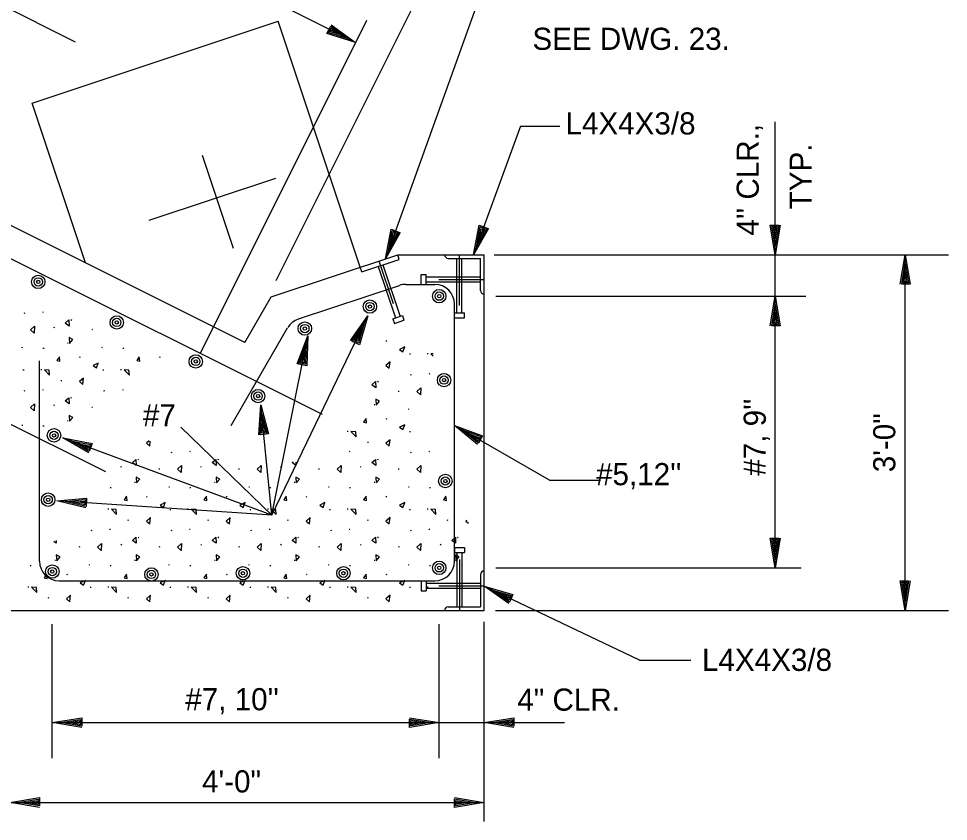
# Model space of a CAD drawing. Extents: x 6 to 106, y 3 to 74.
# Drawn here: x 89.14 to 104.82, y 24.53 to 38.07 of the extents above; entities that cross this region are included whole.
import ezdxf

# ---------------------------------------------------------------- set-up
doc = ezdxf.new("R2010")
doc.units = 0
for name, color, linetype in [('Level 22', 7, 'Continuous'), ('Level 25', 7, 'Continuous'), ('Level 3', 7, 'Continuous'), ('Level 44', 7, 'Continuous'), ('Level 50', 7, 'Continuous')]:
    doc.layers.add(name, color=color, linetype=linetype)

msp = doc.modelspace()

# ---------------------------------------------------------------- linework, layer by layer
at = {"layer": 'Level 22'}
for p, q in [((94.822, 37.665), (82.747, 43.702)), ((90.1, 37.67), (82.326, 41.557)), ((92.955, 32.603), (79.753, 39.204)), ((96.004, 38.701), (93.476, 33.644)), ((94.265, 31.389), (80.275, 38.384)), ((96.855, 38.273), (95.329, 34.019)), ((95.008, 38.037), (92.2, 32.422)), ((97.603, 36.251), (96.813, 34.086)), ((97.603, 36.251), (98.266, 36.251)), ((101.9, 34.086), (101.9, 36.324)), ((90.607, 30.423), (79.157, 36.148)), ((97.159, 34.086), (104.821, 34.086)), ((95.203, 33.889), (95.493, 33.019)), ((95.216, 33.981), (95.456, 33.262)), ((95.282, 33.915), (95.572, 33.046)), ((97.187, 33.387), (102.416, 33.387)), ((95.453, 33.006), (95.48, 32.927)), ((95.611, 33.059), (95.638, 32.98)), ((93.409, 29.696), (91.876, 31.177)), ((98.09, 30.286), (98.955, 30.286)), ((97.187, 28.806), (102.339, 28.806)), ((99.611, 27.249), (96.991, 28.495)), ((97.18, 28.086), (104.821, 28.086)), ((89.707, 25.596), (89.707, 27.857)), ((99.611, 27.249), (100.476, 27.249)), ((89.707, 26.195), (96.233, 26.195)), ((96.233, 26.195), (96.991, 26.195)), ((96.991, 26.195), (98.347, 26.195)), ((88.991, 24.85), (96.991, 24.85))]:
    msp.add_line(p, q, dxfattribs=at)
for centre, radius, start, end in [((96.386, 34.086), 0.0625, 180, 270), ((95.667, 33.253), 0.333, 90, 108.4348), ((96.157, 33.253), 0.333, 0, 90), ((96.991, 33.482), 0.0625, 180, 270), ((93.965, 32.685), 0.333, 108.435, 149.9988), ((89.824, 28.92), 0.333, 180, 270), ((96.157, 28.92), 0.333, 270, 0), ((96.991, 28.691), 0.0625, 90, 180), ((96.386, 28.086), 0.0625, 90, 180)]:
    msp.add_arc(centre, radius, start, end, dxfattribs=at)
at = {"layer": 'Level 25'}
for p, q in [((89.366, 36.643), (93.516, 38.026)), ((94.9, 33.876), (93.516, 38.026)), ((90.264, 33.949), (89.366, 36.643)), ((92.761, 34.193), (92.238, 35.761)), ((91.341, 34.666), (93.476, 35.378)), ((93.401, 33.376), (95.532, 34.086)), ((95.532, 34.086), (96.991, 34.086)), ((95.559, 34.007), (95.532, 34.086)), ((96.574, 33.227), (96.574, 34.086)), ((96.991, 28.086), (96.991, 34.086)), ((101.9, 33.387), (101.9, 34.086)), ((104.092, 28.086), (104.092, 34.086)), ((94.926, 33.797), (94.9, 33.876)), ((94.926, 33.797), (95.559, 34.007)), ((96.386, 34.024), (96.928, 34.024)), ((96.532, 33.107), (96.532, 34.024)), ((96.616, 33.107), (96.616, 34.024)), ((96.928, 33.482), (96.928, 34.024)), ((95.928, 33.586), (95.928, 33.753)), ((95.928, 33.753), (96.011, 33.753)), ((96.011, 33.586), (96.011, 33.753)), ((93.859, 33.002), (95.562, 33.569)), ((95.667, 33.586), (96.157, 33.586)), ((95.928, 33.586), (96.011, 33.586)), ((96.011, 33.711), (96.928, 33.711)), ((96.011, 33.628), (96.928, 33.628)), ((96.227, 33.67), (96.991, 33.67)), ((92.955, 32.603), (93.401, 33.376)), ((96.491, 28.92), (96.491, 33.253)), ((101.9, 28.806), (101.9, 33.387)), ((96.491, 33.107), (96.657, 33.107)), ((96.491, 33.024), (96.491, 33.107)), ((96.657, 33.024), (96.657, 33.107)), ((95.453, 33.006), (95.611, 33.059)), ((95.48, 32.927), (95.638, 32.98)), ((96.491, 33.024), (96.657, 33.024)), ((92.725, 31.205), (93.676, 32.852)), ((89.491, 28.92), (89.491, 32.294)), ((96.491, 29.149), (96.657, 29.149)), ((96.491, 29.149), (96.491, 29.066)), ((96.491, 29.066), (96.657, 29.066)), ((96.532, 29.066), (96.532, 28.149)), ((96.616, 29.066), (96.616, 28.149)), ((96.657, 29.149), (96.657, 29.066)), ((96.574, 28.946), (96.574, 28.086)), ((89.824, 28.586), (96.157, 28.586)), ((95.928, 28.586), (95.928, 28.42)), ((95.928, 28.586), (96.011, 28.586)), ((96.011, 28.586), (96.011, 28.42)), ((96.011, 28.545), (96.928, 28.545)), ((96.928, 28.691), (96.928, 28.149)), ((95.928, 28.42), (96.011, 28.42)), ((96.011, 28.461), (96.928, 28.461)), ((96.227, 28.503), (96.991, 28.503)), ((88.991, 28.086), (96.991, 28.086)), ((96.386, 28.149), (96.928, 28.149)), ((96.233, 25.596), (96.233, 27.857)), ((96.991, 24.53), (96.991, 27.893))]:
    msp.add_line(p, q, dxfattribs=at)
at = {"layer": 'Level 3'}
for p, q in [((93.409, 29.696), (95.028, 33.054)), ((95.028, 33.054), (95.028, 33.054)), ((94.968, 32.929), (94.968, 32.929)), ((93.409, 29.696), (94.016, 32.717)), ((94.016, 32.717), (94.016, 32.717)), ((93.989, 32.581), (93.989, 32.581)), ((93.409, 29.696), (93.224, 31.552)), ((93.224, 31.552), (93.224, 31.552)), ((93.237, 31.414), (93.237, 31.414)), ((93.409, 29.696), (89.884, 30.996)), ((89.884, 30.996), (89.884, 30.996)), ((90.014, 30.948), (90.014, 30.948)), ((93.409, 29.696), (89.783, 29.933)), ((89.783, 29.933), (89.783, 29.933)), ((89.921, 29.924), (89.921, 29.924))]:
    msp.add_line(p, q, dxfattribs=at)
for points in [[(94.737, 32.641), (95.028, 33.054), (94.886, 32.569), (94.759, 32.63), (94.968, 32.929), (94.871, 32.6), (94.79, 32.639), (94.91, 32.809), (94.857, 32.631), (94.823, 32.647), (94.85, 32.684)], [(93.837, 32.244), (94.016, 32.717), (93.999, 32.211), (93.86, 32.239), (93.989, 32.581), (93.977, 32.238), (93.888, 32.256), (93.963, 32.45), (93.955, 32.264), (93.919, 32.271), (93.935, 32.314)], [(93.191, 31.048), (93.224, 31.552), (93.355, 31.064), (93.215, 31.05), (93.237, 31.414), (93.327, 31.083), (93.237, 31.074), (93.251, 31.282), (93.298, 31.102), (93.261, 31.098), (93.264, 31.144)], [(90.323, 30.746), (89.884, 30.996), (90.38, 30.901), (90.331, 30.768), (90.014, 30.948), (90.351, 30.883), (90.32, 30.798), (90.139, 30.901), (90.322, 30.865), (90.309, 30.83), (90.269, 30.854)], [(90.275, 29.818), (89.783, 29.933), (90.286, 29.983), (90.276, 29.842), (89.921, 29.924), (90.263, 29.957), (90.257, 29.867), (90.054, 29.915), (90.24, 29.932), (90.237, 29.895), (90.192, 29.906)]]:
    msp.add_lwpolyline(points, dxfattribs=at)
at = {"layer": 'Level 44'}
for p, q in [((89.244, 33.101), (89.226, 33.096)), ((89.555, 33.119), (89.542, 33.114)), ((90.037, 32.978), (90.022, 32.987)), ((89.747, 32.854), (89.733, 32.86)), ((90.387, 32.822), (90.372, 32.82)), ((95.349, 32.631), (95.333, 32.623)), ((89.208, 32.517), (89.195, 32.519)), ((89.567, 32.505), (89.549, 32.505)), ((89.977, 32.595), (89.964, 32.596)), ((90.555, 32.517), (90.542, 32.519)), ((90.914, 32.505), (90.896, 32.505)), ((90.178, 32.36), (90.162, 32.352)), ((91.524, 32.36), (91.508, 32.352)), ((95.747, 32.41), (95.729, 32.41)), ((96.046, 32.416), (96.029, 32.416)), ((89.23, 32.138), (89.212, 32.138)), ((89.528, 32.145), (89.511, 32.145)), ((90.576, 32.138), (90.558, 32.138)), ((90.875, 32.145), (90.858, 32.145)), ((95.762, 32.061), (95.744, 32.056)), ((96.072, 32.079), (96.059, 32.074)), ((89.868, 31.958), (89.85, 31.961)), ((95.208, 31.937), (95.193, 31.946)), ((89.244, 31.789), (89.226, 31.784)), ((89.555, 31.807), (89.542, 31.802)), ((90.591, 31.789), (90.573, 31.784)), ((90.901, 31.807), (90.888, 31.802)), ((95.558, 31.781), (95.543, 31.78)), ((89.747, 31.542), (89.733, 31.549)), ((90.037, 31.666), (90.022, 31.675)), ((95.148, 31.554), (95.135, 31.555)), ((90.387, 31.51), (90.372, 31.509)), ((95.726, 31.476), (95.713, 31.479)), ((89.977, 31.283), (89.964, 31.284)), ((95.349, 31.319), (95.333, 31.311)), ((89.208, 31.205), (89.195, 31.207)), ((89.567, 31.194), (89.549, 31.194)), ((94.699, 31.104), (94.682, 31.104)), ((95.747, 31.098), (95.729, 31.098)), ((98.09, 30.286), (96.491, 31.208)), ((95.039, 30.918), (95.021, 30.921)), ((91.722, 30.749), (91.704, 30.744)), ((92.032, 30.767), (92.019, 30.762)), ((94.726, 30.767), (94.713, 30.762)), ((95.762, 30.749), (95.744, 30.744)), ((96.07, 30.766), (96.059, 30.762)), ((91.168, 30.626), (91.153, 30.635)), ((92.515, 30.626), (92.5, 30.635)), ((95.208, 30.626), (95.193, 30.635)), ((90.878, 30.502), (90.864, 30.508)), ((91.518, 30.47), (91.503, 30.468)), ((92.225, 30.502), (92.21, 30.508)), ((92.864, 30.47), (92.85, 30.468)), ((93.571, 30.502), (93.557, 30.508)), ((94.211, 30.47), (94.196, 30.468)), ((94.918, 30.502), (94.904, 30.508)), ((95.558, 30.47), (95.543, 30.468)), ((90.698, 30.153), (90.68, 30.153)), ((91.108, 30.243), (91.095, 30.244)), ((91.686, 30.165), (91.673, 30.167)), ((92.045, 30.153), (92.027, 30.153)), ((92.455, 30.243), (92.442, 30.244)), ((93.033, 30.165), (93.019, 30.167)), ((93.391, 30.153), (93.373, 30.153)), ((93.802, 30.243), (93.788, 30.244)), ((94.379, 30.165), (94.366, 30.167)), ((94.738, 30.153), (94.72, 30.153)), ((95.148, 30.243), (95.135, 30.244)), ((95.726, 30.165), (95.713, 30.167)), ((96.085, 30.153), (96.067, 30.153)), ((91.309, 30.008), (91.293, 30)), ((92.655, 30.008), (92.639, 30)), ((94.002, 30.008), (93.986, 30)), ((95.349, 30.008), (95.333, 30)), ((90.659, 29.793), (90.642, 29.793)), ((91.707, 29.786), (91.689, 29.786)), ((92.006, 29.793), (91.989, 29.793)), ((93.054, 29.786), (93.036, 29.786)), ((93.353, 29.793), (93.336, 29.793)), ((94.401, 29.786), (94.383, 29.786)), ((94.699, 29.793), (94.682, 29.793)), ((95.747, 29.786), (95.729, 29.786)), ((96.046, 29.793), (96.029, 29.793)), ((90.999, 29.606), (90.981, 29.609)), ((92.345, 29.606), (92.328, 29.609)), ((93.692, 29.606), (93.675, 29.609)), ((95.039, 29.606), (95.021, 29.609)), ((96.385, 29.606), (96.368, 29.609)), ((90.375, 29.437), (90.357, 29.432)), ((90.686, 29.455), (90.673, 29.45)), ((91.722, 29.437), (91.704, 29.432)), ((92.032, 29.455), (92.019, 29.45)), ((93.068, 29.437), (93.05, 29.432)), ((93.379, 29.455), (93.366, 29.45)), ((94.415, 29.437), (94.397, 29.432)), ((94.726, 29.455), (94.713, 29.45)), ((95.762, 29.437), (95.744, 29.432)), ((96.072, 29.455), (96.059, 29.45)), ((90.878, 29.19), (90.864, 29.197)), ((91.168, 29.314), (91.153, 29.323)), ((92.225, 29.19), (92.21, 29.197)), ((92.515, 29.314), (92.5, 29.323)), ((93.571, 29.19), (93.557, 29.197)), ((93.862, 29.314), (93.847, 29.323)), ((94.918, 29.19), (94.904, 29.197)), ((95.208, 29.314), (95.193, 29.323)), ((96.265, 29.19), (96.25, 29.197)), ((96.555, 29.314), (96.54, 29.323)), ((90.171, 29.158), (90.156, 29.157)), ((91.518, 29.158), (91.503, 29.157)), ((92.864, 29.158), (92.85, 29.157)), ((94.211, 29.158), (94.196, 29.157)), ((95.558, 29.158), (95.543, 29.157)), ((89.762, 28.931), (89.748, 28.932)), ((91.108, 28.931), (91.095, 28.932)), ((92.455, 28.931), (92.442, 28.932)), ((93.802, 28.931), (93.788, 28.932)), ((95.148, 28.931), (95.135, 28.932)), ((96.495, 28.931), (96.482, 28.932)), ((89.351, 28.842), (89.333, 28.842)), ((90.339, 28.853), (90.326, 28.855)), ((90.698, 28.842), (90.68, 28.842)), ((91.686, 28.853), (91.673, 28.855)), ((92.045, 28.842), (92.027, 28.842)), ((93.033, 28.853), (93.019, 28.855)), ((93.391, 28.842), (93.373, 28.842)), ((94.379, 28.853), (94.366, 28.855)), ((94.738, 28.842), (94.72, 28.842)), ((95.726, 28.853), (95.713, 28.855)), ((96.085, 28.842), (96.067, 28.842)), ((89.962, 28.696), (89.946, 28.688)), ((91.309, 28.696), (91.293, 28.688)), ((92.655, 28.696), (92.639, 28.688)), ((94.002, 28.696), (93.986, 28.688)), ((95.349, 28.696), (95.333, 28.688)), ((89.313, 28.481), (89.296, 28.481)), ((90.361, 28.475), (90.343, 28.475)), ((90.659, 28.481), (90.642, 28.481)), ((91.707, 28.475), (91.689, 28.475)), ((92.006, 28.481), (91.989, 28.481)), ((93.054, 28.475), (93.036, 28.475)), ((93.353, 28.481), (93.336, 28.481)), ((94.401, 28.475), (94.383, 28.475)), ((94.699, 28.481), (94.682, 28.481)), ((95.747, 28.475), (95.729, 28.475)), ((96.046, 28.481), (96.029, 28.481)), ((89.652, 28.295), (89.635, 28.298)), ((90.999, 28.295), (90.981, 28.298)), ((92.345, 28.295), (92.328, 28.298)), ((93.692, 28.295), (93.675, 28.298)), ((95.039, 28.295), (95.021, 28.298))]:
    msp.add_line(p, q, dxfattribs=at)
for points in [[(89.99, 32.883), (89.926, 32.932), (89.987, 32.986)], [(89.4, 32.763), (89.339, 32.82), (89.407, 32.881)], [(89.997, 32.59), (90.054, 32.654), (89.99, 32.688)], [(95.621, 32.449), (95.653, 32.53), (95.565, 32.487)], [(89.836, 32.292), (89.827, 32.365), (89.786, 32.304)], [(91.183, 32.292), (91.174, 32.365), (91.133, 32.304)], [(90.45, 32.177), (90.482, 32.259), (90.394, 32.216)], [(95.403, 32.278), (95.334, 32.218), (95.391, 32.17)], [(89.653, 32.14), (89.573, 32.145), (89.66, 32.056)], [(90.232, 32.006), (90.163, 31.947), (90.22, 31.899)], [(91, 32.14), (90.92, 32.145), (91.007, 32.056)], [(95.161, 31.843), (95.097, 31.891), (95.158, 31.946)], [(95.918, 31.723), (95.856, 31.78), (95.925, 31.841)], [(89.4, 31.451), (89.339, 31.508), (89.407, 31.569)], [(89.99, 31.572), (89.926, 31.62), (89.987, 31.674)], [(95.168, 31.55), (95.225, 31.614), (95.161, 31.648)], [(89.997, 31.278), (90.054, 31.342), (89.99, 31.376)], [(95.007, 31.252), (94.998, 31.325), (94.957, 31.264)], [(95.621, 31.137), (95.653, 31.219), (95.565, 31.176)], [(94.824, 31.1), (94.744, 31.104), (94.831, 31.016)], [(95.403, 30.966), (95.334, 30.906), (95.391, 30.859)], [(91.121, 30.531), (91.057, 30.58), (91.118, 30.634)], [(92.468, 30.531), (92.404, 30.58), (92.465, 30.634)], [(95.161, 30.531), (95.097, 30.58), (95.158, 30.634)], [(91.878, 30.411), (91.816, 30.468), (91.885, 30.529)], [(93.225, 30.411), (93.163, 30.468), (93.231, 30.529)], [(94.571, 30.411), (94.51, 30.468), (94.578, 30.529)], [(95.918, 30.411), (95.856, 30.468), (95.925, 30.529)], [(91.128, 30.238), (91.185, 30.302), (91.121, 30.336)], [(92.474, 30.238), (92.531, 30.302), (92.468, 30.336)], [(93.821, 30.238), (93.878, 30.302), (93.814, 30.336)], [(95.168, 30.238), (95.225, 30.302), (95.161, 30.336)], [(90.967, 29.94), (90.958, 30.013), (90.917, 29.952)], [(92.314, 29.94), (92.305, 30.013), (92.264, 29.952)], [(93.661, 29.94), (93.651, 30.013), (93.61, 29.952)], [(95.007, 29.94), (94.998, 30.013), (94.957, 29.952)], [(96.354, 29.94), (96.345, 30.013), (96.304, 29.952)], [(91.581, 29.825), (91.613, 29.907), (91.525, 29.864)], [(92.928, 29.825), (92.96, 29.907), (92.871, 29.864)], [(94.275, 29.825), (94.306, 29.907), (94.218, 29.864)], [(95.621, 29.825), (95.653, 29.907), (95.565, 29.864)], [(90.784, 29.788), (90.704, 29.793), (90.791, 29.704)], [(91.363, 29.654), (91.294, 29.595), (91.351, 29.547)], [(92.131, 29.788), (92.051, 29.793), (92.138, 29.704)], [(92.709, 29.654), (92.641, 29.595), (92.698, 29.547)], [(93.478, 29.788), (93.398, 29.793), (93.484, 29.704)], [(94.056, 29.654), (93.988, 29.595), (94.044, 29.547)], [(94.824, 29.788), (94.744, 29.793), (94.831, 29.704)], [(95.403, 29.654), (95.334, 29.595), (95.391, 29.547)], [(96.171, 29.788), (96.091, 29.793), (96.178, 29.704)], [(90.531, 29.099), (90.47, 29.156), (90.538, 29.217)], [(91.121, 29.22), (91.057, 29.268), (91.118, 29.322)], [(91.878, 29.099), (91.816, 29.156), (91.885, 29.217)], [(92.468, 29.22), (92.404, 29.268), (92.465, 29.322)], [(93.225, 29.099), (93.163, 29.156), (93.231, 29.217)], [(93.814, 29.22), (93.75, 29.268), (93.812, 29.322)], [(94.571, 29.099), (94.51, 29.156), (94.578, 29.217)], [(95.161, 29.22), (95.097, 29.268), (95.158, 29.322)], [(95.918, 29.099), (95.856, 29.156), (95.925, 29.217)], [(96.508, 29.22), (96.444, 29.268), (96.505, 29.322)], [(89.781, 28.926), (89.838, 28.99), (89.774, 29.024)], [(91.128, 28.926), (91.185, 28.99), (91.121, 29.024)], [(92.474, 28.926), (92.531, 28.99), (92.468, 29.024)], [(93.821, 28.926), (93.878, 28.99), (93.814, 29.024)], [(95.168, 28.926), (95.225, 28.99), (95.161, 29.024)], [(96.514, 28.926), (96.571, 28.99), (96.508, 29.024)], [(89.621, 28.628), (89.611, 28.701), (89.57, 28.64)], [(90.967, 28.628), (90.958, 28.701), (90.917, 28.64)], [(92.314, 28.628), (92.305, 28.701), (92.264, 28.64)], [(93.661, 28.628), (93.651, 28.701), (93.61, 28.64)], [(95.007, 28.628), (94.998, 28.701), (94.957, 28.64)], [(90.235, 28.514), (90.266, 28.595), (90.178, 28.552)], [(91.581, 28.514), (91.613, 28.595), (91.525, 28.552)], [(92.928, 28.514), (92.96, 28.595), (92.871, 28.552)], [(94.275, 28.514), (94.306, 28.595), (94.218, 28.552)], [(95.621, 28.514), (95.653, 28.595), (95.565, 28.552)], [(89.438, 28.477), (89.358, 28.481), (89.444, 28.392)], [(90.784, 28.477), (90.704, 28.481), (90.791, 28.392)], [(92.131, 28.477), (92.051, 28.481), (92.138, 28.392)], [(93.478, 28.477), (93.398, 28.481), (93.484, 28.392)], [(94.824, 28.477), (94.744, 28.481), (94.831, 28.392)], [(90.016, 28.343), (89.948, 28.283), (90.004, 28.235)], [(91.363, 28.343), (91.294, 28.283), (91.351, 28.235)], [(92.709, 28.343), (92.641, 28.283), (92.698, 28.235)], [(94.056, 28.343), (93.988, 28.283), (94.044, 28.235)], [(95.403, 28.343), (95.334, 28.283), (95.391, 28.235)]]:
    msp.add_lwpolyline(points, close=True, dxfattribs=at)
for points in [[(96.133, 32.414), (96.091, 32.416), (96.129, 32.377)], [(91.339, 30.945), (91.294, 30.906), (91.351, 30.859), (91.36, 30.942)], [(93.814, 30.531), (93.75, 30.58), (93.768, 30.596)], [(93.813, 30.589), (93.814, 30.531)], [(96.698, 29.609), (96.681, 29.595), (96.726, 29.557)], [(89.774, 29.22), (89.735, 29.249)], [(89.773, 29.264), (89.774, 29.22)]]:
    msp.add_lwpolyline(points, dxfattribs=at)
at = {"layer": 'Level 50'}
for p, q in [((94.698, 37.727), (94.698, 37.727)), ((94.822, 37.665), (94.822, 37.665)), ((96.861, 34.217), (96.861, 34.217)), ((101.9, 34.225), (101.9, 34.225)), ((95.376, 34.149), (95.376, 34.149)), ((96.813, 34.086), (96.813, 34.086)), ((101.9, 34.086), (101.9, 34.086)), ((104.092, 34.086), (104.092, 34.086)), ((95.329, 34.019), (95.329, 34.019)), ((104.092, 33.948), (104.092, 33.948)), ((101.9, 33.387), (101.9, 33.387)), ((101.9, 33.249), (101.9, 33.249)), ((96.491, 31.208), (96.491, 31.208)), ((96.611, 31.138), (96.611, 31.138)), ((101.9, 28.944), (101.9, 28.944)), ((101.9, 28.806), (101.9, 28.806)), ((96.991, 28.495), (96.991, 28.495)), ((97.116, 28.436), (97.116, 28.436)), ((104.092, 28.225), (104.092, 28.225)), ((104.092, 28.086), (104.092, 28.086)), ((89.707, 26.195), (89.707, 26.195)), ((89.845, 26.195), (89.845, 26.195)), ((96.094, 26.195), (96.094, 26.195)), ((96.233, 26.195), (96.233, 26.195)), ((96.991, 26.195), (96.991, 26.195)), ((97.129, 26.195), (97.129, 26.195)), ((96.852, 24.85), (96.852, 24.85)), ((96.991, 24.85), (96.991, 24.85))]:
    msp.add_line(p, q, dxfattribs=at)
for points in [[(94.413, 37.962), (94.822, 37.665), (94.339, 37.814), (94.402, 37.94), (94.698, 37.727), (94.37, 37.828), (94.41, 37.909), (94.579, 37.786), (94.401, 37.842), (94.418, 37.876), (94.454, 37.848)], [(95.575, 34.46), (95.329, 34.019), (95.42, 34.516), (95.553, 34.468), (95.376, 34.149), (95.438, 34.487), (95.523, 34.456), (95.421, 34.275), (95.456, 34.458), (95.491, 34.445), (95.468, 34.405)], [(97.062, 34.527), (96.813, 34.086), (96.906, 34.583), (97.039, 34.535), (96.861, 34.217), (96.924, 34.554), (97.009, 34.523), (96.906, 34.342), (96.942, 34.525), (96.977, 34.512), (96.954, 34.472)], [(101.983, 34.585), (101.9, 34.086), (101.817, 34.585), (101.959, 34.585), (101.9, 34.225), (101.844, 34.564), (101.935, 34.564), (101.9, 34.358), (101.871, 34.542), (101.908, 34.542), (101.9, 34.497)], [(104.009, 33.588), (104.092, 34.086), (104.174, 33.588), (104.033, 33.588), (104.092, 33.948), (104.148, 33.609), (104.057, 33.609), (104.092, 33.814), (104.121, 33.63), (104.084, 33.63), (104.092, 33.676)], [(101.817, 32.889), (101.9, 33.387), (101.983, 32.889), (101.841, 32.889), (101.9, 33.249), (101.956, 32.91), (101.865, 32.91), (101.9, 33.115), (101.929, 32.931), (101.892, 32.931), (101.9, 32.977)], [(96.881, 30.887), (96.491, 31.208), (96.964, 31.03), (96.893, 30.908), (96.611, 31.138), (96.932, 31.018), (96.887, 30.939), (96.726, 31.072), (96.9, 31.005), (96.882, 30.973), (96.846, 31.003)], [(101.983, 29.304), (101.9, 28.806), (101.817, 29.304), (101.959, 29.304), (101.9, 28.944), (101.844, 29.283), (101.935, 29.283), (101.9, 29.078), (101.871, 29.262), (101.908, 29.262), (101.9, 29.216)], [(104.174, 28.585), (104.092, 28.086), (104.009, 28.585), (104.15, 28.585), (104.092, 28.225), (104.036, 28.564), (104.126, 28.564), (104.092, 28.358), (104.062, 28.542), (104.1, 28.542), (104.092, 28.497)], [(97.405, 28.206), (96.991, 28.495), (97.476, 28.356), (97.416, 28.228), (97.116, 28.436), (97.446, 28.341), (97.407, 28.259), (97.236, 28.378), (97.415, 28.326), (97.399, 28.292), (97.361, 28.319)], [(90.205, 26.112), (89.707, 26.195), (90.205, 26.278), (90.205, 26.136), (89.845, 26.195), (90.184, 26.251), (90.184, 26.16), (89.979, 26.195), (90.163, 26.224), (90.163, 26.187), (90.117, 26.195)], [(95.734, 26.278), (96.233, 26.195), (95.734, 26.112), (95.734, 26.254), (96.094, 26.195), (95.755, 26.139), (95.755, 26.23), (95.961, 26.195), (95.777, 26.166), (95.777, 26.203), (95.822, 26.195)], [(97.489, 26.112), (96.991, 26.195), (97.489, 26.278), (97.489, 26.136), (97.129, 26.195), (97.468, 26.251), (97.468, 26.16), (97.263, 26.195), (97.447, 26.224), (97.447, 26.187), (97.401, 26.195)], [(89.489, 24.767), (88.991, 24.85), (89.489, 24.933), (89.489, 24.791), (89.129, 24.85), (89.468, 24.906), (89.468, 24.815), (89.263, 24.85), (89.447, 24.879), (89.447, 24.842), (89.401, 24.85)], [(96.492, 24.933), (96.991, 24.85), (96.492, 24.767), (96.492, 24.909), (96.852, 24.85), (96.513, 24.794), (96.513, 24.885), (96.719, 24.85), (96.535, 24.821), (96.535, 24.858), (96.58, 24.85)]]:
    msp.add_lwpolyline(points, dxfattribs=at)
for centre, radius in [((89.469, 33.628), 0.113), ((89.469, 33.628), 0.0703), ((89.469, 33.628), 0.0281), ((96.233, 33.387), 0.113), ((96.233, 33.387), 0.0703), ((96.233, 33.387), 0.0281), ((95.063, 33.212), 0.113), ((95.063, 33.212), 0.0703), ((95.063, 33.212), 0.0281), ((90.795, 32.944), 0.113), ((90.795, 32.944), 0.0703), ((90.795, 32.944), 0.0281), ((93.966, 32.841), 0.113), ((93.966, 32.841), 0.0703), ((93.966, 32.841), 0.0281), ((92.126, 32.286), 0.113), ((92.126, 32.286), 0.0703), ((92.126, 32.286), 0.0281), ((96.314, 31.972), 0.113), ((96.314, 31.972), 0.0703), ((96.314, 31.972), 0.0281), ((93.178, 31.702), 0.113), ((93.178, 31.702), 0.0703), ((93.178, 31.702), 0.0281), ((89.736, 31.04), 0.113), ((89.736, 31.04), 0.0703), ((89.736, 31.04), 0.0281), ((96.336, 30.27), 0.113), ((96.336, 30.27), 0.0703), ((96.336, 30.27), 0.0281), ((89.637, 29.955), 0.113), ((89.637, 29.955), 0.0703), ((89.637, 29.955), 0.0281), ((96.233, 28.806), 0.113), ((96.233, 28.806), 0.0703), ((89.707, 28.743), 0.113), ((89.707, 28.743), 0.0703), ((89.707, 28.743), 0.0281), ((91.379, 28.694), 0.113), ((91.379, 28.694), 0.0703), ((91.379, 28.694), 0.0281), ((92.923, 28.715), 0.113), ((92.923, 28.715), 0.0703), ((92.923, 28.715), 0.0281), ((94.617, 28.715), 0.113), ((94.617, 28.715), 0.0703), ((94.617, 28.715), 0.0281), ((96.233, 28.806), 0.0281)]:
    msp.add_circle(centre, radius, dxfattribs=at)

# ---------------------------------------------------------------- texts
at = {"layer": 'Level 22'}
for s, height, p in [('SEE DWG. 23.', 0.37333, (97.805, 37.54)), ('L4X4X3/8', 0.3733, (98.363, 36.113)), ('#7', 0.3733, (91.235, 31.191)), ("#5,12''", 0.3733, (98.878, 30.199)), ('L4X4X3/8', 0.3733, (100.665, 27.068)), ("#7, 10''", 0.3733, (91.95, 26.404)), ('4" CLR.', 0.3733, (97.55, 26.397)), ('4\'-0"', 0.3733, (92.233, 25.018))]:
    msp.add_text(s, height=height, dxfattribs=at).set_placement(p)
for s, p in [("4'' CLR.,", (101.623, 34.409)), ('TYP.', (102.517, 34.852)), ("#7, 9''", (101.741, 30.359)), ('3\'-0"', (103.925, 30.418))]:
    msp.add_text(s, height=0.3733, rotation=90, dxfattribs=at).set_placement(p)

doc.saveas('drawing.dxf')
